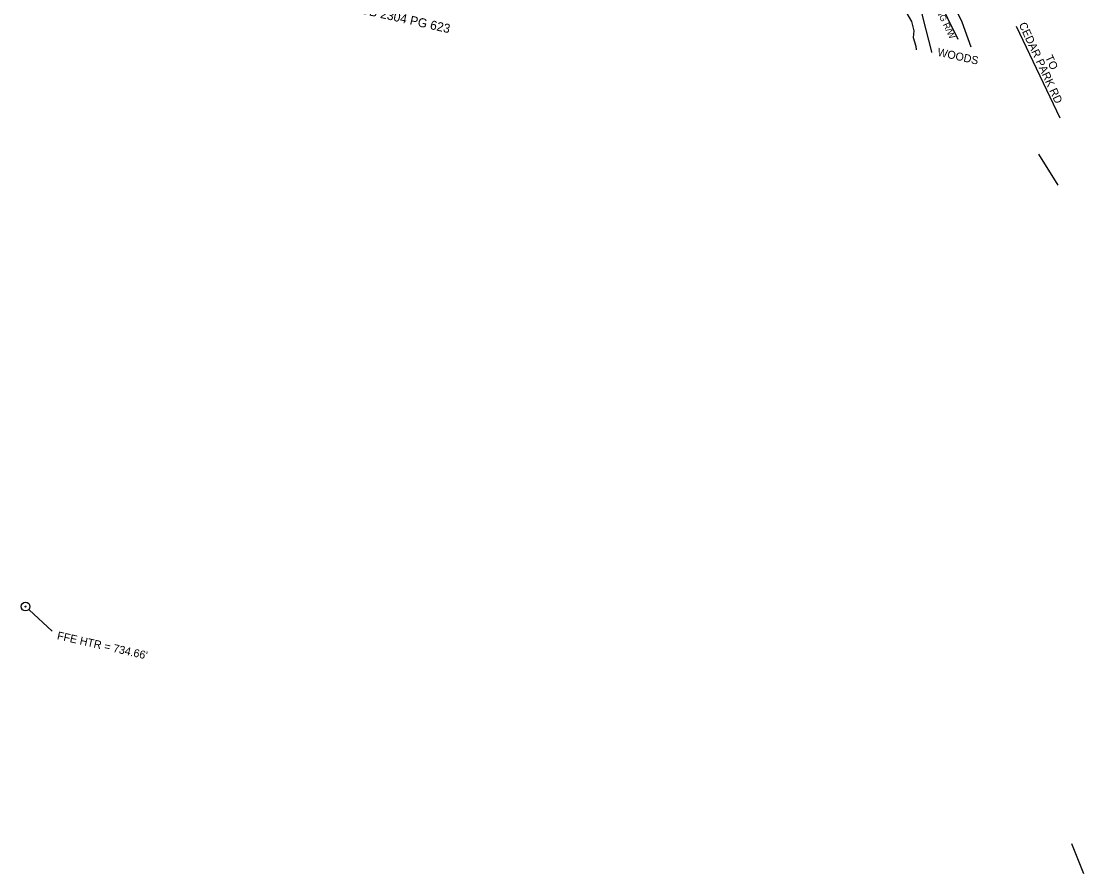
# Model space of a CAD drawing. Extents: x 1784037 to 1786391, y 840555 to 842045.
# Drawn here: x 1785231 to 1785762, y 840789 to 841214 of the extents above; entities that cross this region are included whole.
import ezdxf

# ---------------------------------------------------------------- set-up
doc = ezdxf.new("R2010")
doc.units = 0
for name, color, linetype in [('Exist Hydro Stream or Body of Water', 7, 'Continuous'), ('Exist Other Culture Fence Line', 7, 'Continuous'), ('Exist Other Culture Located Object CELL', 7, 'Continuous'), ('Exist Other Culture Located Object Leader', 7, 'Continuous'), ('Exist Other Culture Located Object Text', 7, 'Continuous'), ('Exist Property Deed Book Text', 7, 'Continuous'), ('Exist Right of Way Line', 7, 'Continuous'), ('Exist Right of Way Line Text', 7, 'Continuous'), ('Exist Roads EOP Leader', 7, 'Continuous'), ('Exist Roads EOP Text', 7, 'Continuous'), ('Exist Structure Minor Culvert Topo', 7, 'Continuous'), ('Exist Vegetation Woods Line', 7, 'Continuous'), ('Exist Vegetation Woods Line Text', 7, 'Continuous')]:
    doc.layers.add(name, color=color, linetype=linetype)

msp = doc.modelspace()

# ---------------------------------------------------------------- linework, layer by layer
at = {"layer": 'Exist Hydro Stream or Body of Water'}
msp.add_lwpolyline([(1785673.33, 841218.11), (1785675.67, 841214.02), (1785676.86, 841209.45), (1785676.58, 841206.02), (1785677.92, 841201.76), (1785677.99, 841199.92)], dxfattribs=at)
at = {"layer": 'Exist Other Culture Fence Line'}
msp.add_lwpolyline([(1785761.79, 840788.61), (1785755.8, 840803.57)], dxfattribs=at)
at = {"layer": 'Exist Other Culture Located Object CELL'}
for radius in [2.18, 0.24]:
    msp.add_circle((1785233.15, 840921.98), radius, dxfattribs=at)
at = {"layer": 'Exist Other Culture Located Object Leader'}
msp.add_line((1785234.89, 840920.36), (1785246.48, 840909.67), dxfattribs=at)
at = {"layer": 'Exist Right of Way Line'}
msp.add_line((1785699.04, 841205.06), (1785680.07, 841243.87), dxfattribs=at)
at = {"layer": 'Exist Roads EOP Leader'}
msp.add_line((1785750.08, 841165.77), (1785728.17, 841211.53), dxfattribs=at)
at = {"layer": 'Exist Structure Minor Culvert Topo'}
msp.add_line((1785748.96, 841132.37), (1785739.32, 841147.9), dxfattribs=at)
at = {"layer": 'Exist Vegetation Woods Line'}
msp.add_lwpolyline([(1785685.97, 841198.54), (1785685.9, 841198.94), (1785681.57, 841215.71), (1785679.02, 841227.02), (1785678.24, 841234.86), (1785681.34, 841238.9), (1785690.57, 841235.03), (1785700.83, 841213.86), (1785705.42, 841201.46)], dxfattribs=at)

# ---------------------------------------------------------------- texts
at = {"layer": 'Exist Other Culture Located Object Text'}
msp.add_text("FFE HTR = 734.66'", height=4, rotation=347.2628, dxfattribs=at).set_placement((1785248.6, 840905.71))
at = {"layer": 'Exist Property Deed Book Text'}
msp.add_text('DB 2304 PG 623', height=4.5, rotation=347.3599, dxfattribs=at).set_placement((1785400.31, 841218.12))
at = {"layer": 'Exist Right of Way Line Text'}
msp.add_text('EXISTING R/W', height=3.2, rotation=296.0474, dxfattribs=at).set_placement((1785682.04, 841231.55))
at = {"layer": 'Exist Roads EOP Text'}
for s, p in [('CEDAR PARK RD', (1785729.23, 841212.56)), ('TO', (1785742.39, 841196.24))]:
    msp.add_text(s, height=4, rotation=294.8886, dxfattribs=at).set_placement(p)
at = {"layer": 'Exist Vegetation Woods Line Text'}
msp.add_text('WOODS', height=4, rotation=347.3599, dxfattribs=at).set_placement((1785688.39, 841197.05))

doc.saveas('drawing.dxf')
